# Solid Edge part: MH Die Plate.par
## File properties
Author: Dan
Template: metric part.par
Last saved by: Dan
Revision: 51
Application: Solid Edge
Material: Steel
Face Style: Steel
Fill Style: ANSI32(Steel)
Virtual Style: Machined steel
Coef. of Thermal Exp: 1.3e-05
Thermal Conductivity: 32.0
Specific Heat: 481.0
Modulus of Elasticity: 199947953000.0
Poisson's Ratio: 0.29
Yield Stress: 262000766.0
Ultimate Stress: 358527364.0
Elongation: 0.0
Density: 7833.000 kg/m^3
Accuracy: 0.990
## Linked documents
Wheel.asm
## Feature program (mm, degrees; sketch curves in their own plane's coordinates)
sketch for "unnamed Protrusion 1" plane through (0, 0, 0) normal (0, 0, 1) x-axis (1, 0, 0)
extrude "unnamed Protrusion 1" add finite 36 along -normal
sketch for "Hole_1" plane through (0, 0, -36) normal (0, 0, -1) x-axis (-1, 0, 0)
hole "Hole_1" diameter 116 through  VBottomAngle = 118 deg
sketch for "unnamed Hole 1" plane through (0, 0, -36) normal (0, 0, -1) x-axis (-1, 0, 0)
hole "unnamed Hole 1" through
sketch for "unnamed Hole 2" plane through (0, 0, -36) normal (0, 0, -1) x-axis (-1, 0, 0)
  hole centre (75, 75) bore radius 58
hole "unnamed Hole 2" through
sketch for "unnamed Hole 3" plane through (0, 0, -36) normal (0, 0, -1) x-axis (-1, 0, 0)
  hole centre (75, -75) bore radius 58
hole "unnamed Hole 3" through
pattern "unnamed Pattern 1" of "Hole_1", "unnamed Hole 1", "unnamed Hole 2", "unnamed Hole 3"
sketch for "Hole_9" plane through (0, 0, -36) normal (0, 0, -1) x-axis (1, 0, 0)
hole "Hole_9" diameter 42 through  CounterBoreDepth = 6 mm; VBottomAngle = 118 deg
sketch for "unnamed Hole 4" plane through (0, 0, -36) normal (0, 0, -1) x-axis (1, 0, 0)
hole "unnamed Hole 4" through
sketch for "unnamed Hole 5" plane through (0, 0, -36) normal (0, 0, -1) x-axis (1, 0, 0)
  hole centre (170, -170) bore radius 21
hole "unnamed Hole 5" through
sketch for "unnamed Hole 6" plane through (0, 0, -36) normal (0, 0, -1) x-axis (1, 0, 0)
  hole centre (-170, -170) bore radius 21
hole "unnamed Hole 6" through
pattern "unnamed Pattern 2" of "Hole_9", "unnamed Hole 4", "unnamed Hole 5", "unnamed Hole 6"
boolean "unnamed Boolean 1"
sketch for "Hole_17" plane through (0, 0, -36) normal (0, 0, -1) x-axis (1, 0, 0)
hole "Hole_17" diameter 20 through  VBottomAngle = 118 deg
sketch for "unnamed Hole 7" plane through (0, 0, -36) normal (0, 0, -1) x-axis (1, 0, 0)
  hole centre (62.5, -27) bore radius 3
hole "unnamed Hole 7" through
sketch for "unnamed Hole 8" plane through (0, 0, -36) normal (0, 0, -1) x-axis (1, 0, 0)
  hole centre (170, 106) bore radius 10
hole "unnamed Hole 8" through
sketch for "unnamed Hole 9" plane through (0, 0, -36) normal (0, 0, -1) x-axis (1, 0, 0)
  hole centre (170, -106) bore radius 10
hole "unnamed Hole 9" through
pattern "unnamed Pattern 3" of "Hole_17", "unnamed Hole 7", "unnamed Hole 8", "unnamed Hole 9"
sketch for "unnamed Cutout 1" #1 plane through (0, 0, 0) normal (0, 0, 1) x-axis (-1, 0, 0)
  hole centre (170, 170) bore radius 21
sketch for "unnamed Cutout 1" #2 plane through (0, 0, 0) normal (0, 0, 1) x-axis (-1, 0, 0)
sketch for "unnamed Cutout 1" #3 plane through (0, 0, 0) normal (0, 0, 1) x-axis (-1, 0, 0)
  circle centre (75, 170) radius 5
sketch for "unnamed Cutout 1" #4 plane through (0, 0, 0) normal (0, 0, 1) x-axis (-1, 0, 0)
extrude "unnamed Cutout 1" cut through along -normal
sketch for "Hole_21" plane through (0, 0, -36) normal (0, 0, -1) x-axis (1, 0, 0)
hole "Hole_21" diameter 12 finite  VBottomAngle = 118 deg
sketch for "unnamed Hole 10" plane through (0, 0, -36) normal (0, 0, -1) x-axis (1, 0, 0)
  hole centre (-170, 0) bore radius 5.053
hole "unnamed Hole 10" finite
sketch for "unnamed Hole 11" plane through (0, 0, -36) normal (0, 0, -1) x-axis (1, 0, 0)
  hole centre (-170, -139) bore radius 5.053
hole "unnamed Hole 11" finite
sketch for "unnamed Hole 12" plane through (0, 0, -36) normal (0, 0, -1) x-axis (1, 0, 0)
  hole centre (170, -139) bore radius 5.053
hole "unnamed Hole 12" finite
sketch for "unnamed Hole 13" plane through (0, 0, -36) normal (0, 0, -1) x-axis (1, 0, 0)
  hole centre (170, 0) bore radius 5.053
hole "unnamed Hole 13" finite
sketch for "unnamed Hole 14" plane through (0, 0, -36) normal (0, 0, -1) x-axis (1, 0, 0)
  hole centre (170, 139) bore radius 5.053
hole "unnamed Hole 14" finite
sketch for "Hole_27" plane through (0, 0, 0) normal (1, 0, 0) x-axis (0, 1, 0)
hole "Hole_27" diameter 6 through  VBottomAngle = 118 deg
sketch for "unnamed Hole 15" plane through (0, 0, 0) normal (1, 0, 0) x-axis (0, 1, 0)
hole "unnamed Hole 15" through
sketch for "unnamed Hole 16" plane through (0, 0, 0) normal (1, 0, 0) x-axis (0, 1, 0)
hole "unnamed Hole 16" through
sketch for "unnamed Hole 17" plane through (0, 0, 0) normal (1, 0, 0) x-axis (0, 1, 0)
hole "unnamed Hole 17" through
delete faces "unnamed DeleteFaces 1"
sketch for "Hole_31" plane through (0, 0, -36) normal (0, 0, -1) x-axis (-1, 0, 0)
hole "Hole_31" diameter 27 finite
sketch for "unnamed Hole 18" plane through (0, 0, -36) normal (0, 0, -1) x-axis (-1, 0, 0)
hole "unnamed Hole 18" finite
sketch for "unnamed Hole 19" plane through (0, 0, -36) normal (0, 0, -1) x-axis (-1, 0, 0)
hole "unnamed Hole 19" finite
sketch for "unnamed Hole 20" plane through (0, 0, -36) normal (0, 0, -1) x-axis (-1, 0, 0)
hole "unnamed Hole 20" finite
pattern "unnamed Pattern 4" of "Hole_31", "unnamed Hole 18", "unnamed Hole 19", "unnamed Hole 20"
sketch for "Hole_35" plane through (198, 0, -18) normal (1, 0, 0) x-axis (0, 1, 0)
hole "Hole_35" diameter 10 finite  VBottomAngle = 118 deg
sketch for "unnamed Hole 21" plane through (198, 0, -18) normal (1, 0, 0) x-axis (0, 1, 0)
  hole centre (-125, 0) bore radius 4.188
hole "unnamed Hole 21" finite
pattern "unnamed Pattern 5" of "Hole_35", "unnamed Hole 21"
mirror "unnamed Mirror 1" of "unnamed Pattern 5"
pattern "unnamed Pattern 6"
pattern "unnamed Pattern 7" of "Hole_21", "unnamed Hole 10", "unnamed Hole 11", "unnamed Hole 12", "unnamed Hole 13", "unnamed Hole 14"
pattern "unnamed Pattern 8" of "Hole_27", "unnamed Hole 15", "unnamed Hole 16", "unnamed Hole 17"
Other named dimensions: "CoordinateSystem_2": Y_Rotation = 90 deg; X_Translation = 75 mm; Y_Translation = 75 mm | "CopyConstruction_1": XScale = 1.015; YScale = 1.008; ZScale = 1.008
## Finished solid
Body 1: solid body, 229 faces, 447 edges, 255 vertices, 16 separate solids.
  Faces by surface: plane 163, cylinder 31, spline 26, cone 9
  Edges by curve: line 341, circle 68, spline 34, curve on surface 4
Body 2: solid body, 229 faces, 447 edges, 255 vertices, 16 separate solids.
  Faces by surface: plane 163, cylinder 31, spline 26, cone 9
  Edges by curve: line 341, circle 68, spline 34, curve on surface 4
Body 3: solid body, 229 faces, 447 edges, 255 vertices, 16 separate solids.
  Faces by surface: plane 163, cylinder 31, spline 26, cone 9
  Edges by curve: line 341, circle 68, spline 34, curve on surface 4
Body 4: solid body, 311 faces, 567 edges, 327 vertices, 16 separate solids, 19 internal voids.
  Faces by surface: plane 196, cylinder 67, spline 36, cone 12
  Edges by curve: line 375, spline 102, circle 80, curve on surface 10
Body 5: solid body, 78 faces, 108 edges, 8 vertices.
  Faces by surface: cylinder 42, plane 18, cone 10, spline 8
  Edges by curve: circle 88, line 12, intersection 8
Bounding box of the edges (mm; curved faces can reach further): 396.000 x 396.000 x 54.820, from (-198, -198, -36) to (198, 198, 18.8199).
Cylindrical faces by radius (mm): R3 x8, R4.188 x4, R5 x4, R5.04 x16, R5.053 x6, R7.5588 x4, R9.5745 x8, R10 x4, R10.5824 x8, R13.5 x4, R13.6059 x8, R15.6218 x8, R15.9497 x8, R17.6371 x1, R17.6373 x1, R21 x4, R21.6693 x8, R22.6773 x16, R23.5 x4, R26.7093 x8, R28.5704 x1, R31.7493 x9, R36.036 x8, R38.304 x16, R38.5862 x16, R41.076 x8, R45.864 x8, R58 x4
Conical faces (half-angle, radius in mm at the cone's reference point): 1.9862 deg R16.1609 x8, 1.9862 deg R18.8591 x8, 59 deg R4.188 x4, 59 deg R5.053 x6, 70.2158 deg R10.5824 x8, 70.2158 deg R14.3315 x4, 70.2158 deg R14.3576 x4, 74.9008 deg R54.45 x1, 74.9012 deg R54.4498 x1, 89.9983 deg R30.7413 x1, 89.999 deg R17.1331 x4
Planar faces by outward normal: +x 101, +y 117, +z 86, -x 101, -y 117, -z 117, oblique 64
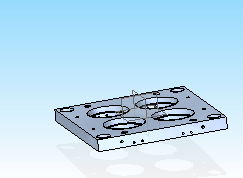
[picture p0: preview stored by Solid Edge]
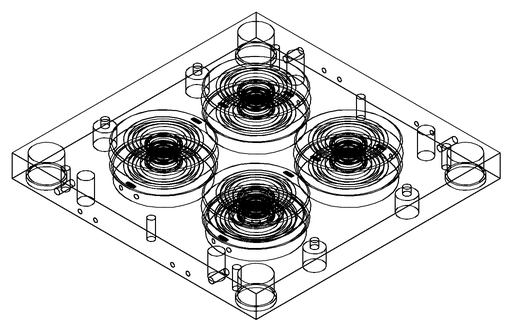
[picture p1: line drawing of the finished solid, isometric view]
